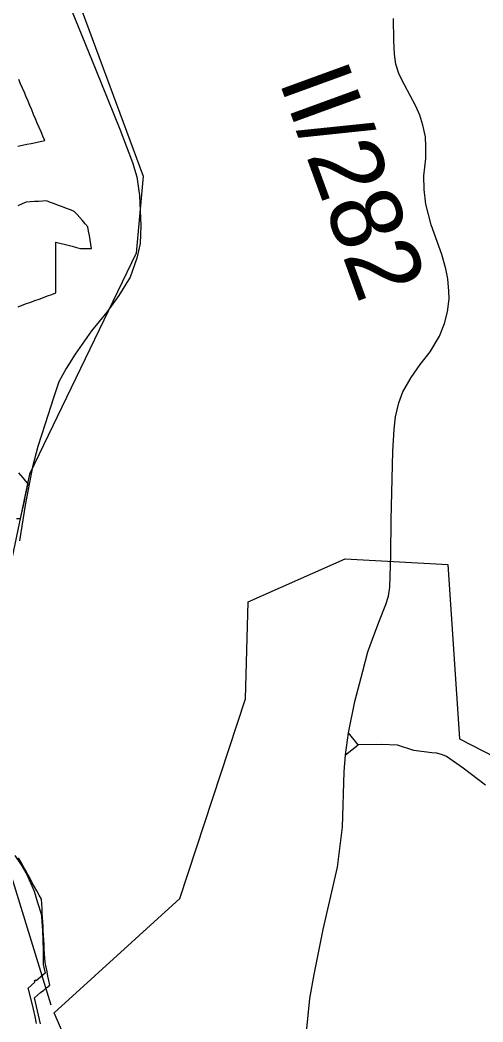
# Model space of a CAD drawing. Extents: x -789162 to -606354, y -1062736 to -945481.
# Drawn here: x -678773 to -677802, y -994612 to -992510 of the extents above; entities that cross this region are included whole.
import ezdxf

# ---------------------------------------------------------------- set-up
doc = ezdxf.new("R2010")
doc.units = 0
for name, color, linetype in [('_SIRSI VZTAHY_CYKLOTRASY MISTNI S', 7, 'Continuous'), ('_SIRSI VZTAHY_NATURA_EVL', 7, 'Continuous'), ('_SIRSI VZTAHY_SILNICE I a II TRIDY_STAV POPIS', 7, 'Continuous'), ('_SIRSI VZTAHY_SILNICE II TRIDY_STAV', 7, 'Continuous'), ('_SIRSI VZTAHY_SILNICE III TRIDY_STAV', 7, 'Continuous'), ('_SIRSI VZTAHY_USES_RBC_S', 7, 'Continuous')]:
    doc.layers.add(name, color=color, linetype=linetype)

msp = doc.modelspace()

# ---------------------------------------------------------------- linework, layer by layer
at = {"layer": '_SIRSI VZTAHY_CYKLOTRASY MISTNI S'}
for points in [[(-678759.8, -990710.2), (-678845.3, -990836.8), (-679139.4, -990833.4), (-679317.2, -990888.2), (-679027.6, -991073.5), (-678942.1, -991337), (-678791.7, -991534), (-678760.9, -991818), (-678830.4, -992067.1), (-678684.3, -992378), (-678514.4, -992837.7), (-678529.1, -992998.8), (-678752.6, -993462.6), (-678839.7, -993873), (-678895.5, -993968.5), (-678708.1, -994576.2)], [(-678593.3, -995993.9), (-678748.9, -995832.2), (-678545.4, -995658.5), (-678527.5, -995508.8), (-678359.9, -995622.6), (-678449.7, -995413), (-678413.8, -995257.3), (-678701, -994592.6), (-678437.7, -994353.1), (-678300, -993933.9), (-678294.1, -993730.3), (-678090.6, -993640.5), (-677875.1, -993652.4), (-677851.2, -994017.7), (-677653.7, -994119.5), (-677432.3, -994053.7), (-677222.8, -993945.9), (-677079.2, -993790.2), (-676932.3, -993551.1), (-676732.1, -993520.7), (-676223.4, -993784.2), (-676067.8, -993418.9), (-675894.3, -993311.1), (-675764.1, -993235.1)]]:
    msp.add_lwpolyline(points, dxfattribs=at)
at = {"layer": '_SIRSI VZTAHY_NATURA_EVL'}
for points in [[(-678776.9, -992774.6), (-678767.6, -992772.6), (-678758.2, -992770.6), (-678748.9, -992768.6), (-678739.5, -992766.6), (-678730.2, -992764.6), (-678720.8, -992762.6), (-678724.7, -992753.5), (-678728.6, -992744.3), (-678732.5, -992735.2), (-678736.4, -992726.1), (-678740.2, -992716.9), (-678744.1, -992707.8), (-678748, -992698.6), (-678751.9, -992689.5), (-678755.7, -992680.3), (-678759.6, -992671.2), (-678763.5, -992662), (-678767.4, -992652.9), (-678771.3, -992643.8), (-678775.1, -992634.6)], [(-678776.6, -993111.3), (-678767.8, -993108.1), (-678759, -993104.9), (-678750.2, -993101.7), (-678741.3, -993098.4), (-678732.5, -993095.2), (-678723.7, -993092), (-678714.8, -993088.8), (-678706, -993085.6), (-678697.2, -993082.4), (-678697.2, -993073.7), (-678697.2, -993064.9), (-678697.3, -993056.2), (-678697.3, -993046.5), (-678697.3, -993036.8), (-678697.4, -993028.1), (-678697.4, -993019.4), (-678697.4, -993010.8), (-678697.5, -993002.1), (-678697.5, -992993.4), (-678697.5, -992984.7), (-678697.6, -992976), (-678688.9, -992978.2), (-678680.3, -992980.3), (-678671.7, -992982.5), (-678663.1, -992984.6), (-678654.4, -992986.8), (-678645.8, -992989), (-678638.1, -992989), (-678630.3, -992989), (-678622.5, -992989), (-678624.1, -992979.9), (-678625.7, -992970.8), (-678627.2, -992961.8), (-678628.8, -992952.7), (-678630.3, -992943.7), (-678636, -992937.2), (-678641.7, -992930.8), (-678647.4, -992924.3), (-678653.1, -992917.8), (-678658.8, -992911.4), (-678667.1, -992908.2), (-678675.4, -992905.1), (-678683.7, -992901.9), (-678692, -992898.8), (-678700.3, -992895.7), (-678708.6, -992892.5), (-678717, -992889.4), (-678725.5, -992889.9), (-678734, -992890.4), (-678742.6, -992890.9), (-678751.1, -992891.4), (-678759.6, -992892), (-678768.4, -992895.8), (-678777.2, -992899.7)], [(-678780.3, -993555.8), (-678771.3, -993555.4), (-678769.3, -993546.3), (-678767.4, -993537.3), (-678765.4, -993528.2), (-678763.5, -993519.2), (-678761.6, -993510.1), (-678759.6, -993501.1), (-678757.7, -993492), (-678755.7, -993483), (-678760.6, -993477.1), (-678765.4, -993471.3), (-678770.3, -993465.5), (-678775.1, -993459.7)], [(-678729.7, -994615.9), (-678731.8, -994606.8), (-678734, -994597.6), (-678736.1, -994588.5), (-678738.2, -994579.3), (-678740.3, -994570.2), (-678742.4, -994561), (-678735.9, -994555.7), (-678729.4, -994550.4), (-678722.9, -994545), (-678716.4, -994539.7), (-678709.8, -994534.4), (-678711.9, -994525), (-678714, -994515.6), (-678716, -994506.1), (-678718.1, -994496.7), (-678720.1, -994487.3), (-678720.7, -994477.8), (-678721.2, -994468.3), (-678721.7, -994458.8), (-678722.3, -994449.3), (-678722.8, -994439.9), (-678723.3, -994430.4), (-678723.8, -994420.9), (-678724.4, -994411.4), (-678724.9, -994402), (-678725.4, -994392.5), (-678725.9, -994383), (-678726.5, -994373.5), (-678727, -994364.1), (-678727.5, -994354.6), (-678732.3, -994345.9), (-678737.2, -994337.1), (-678742, -994328.4), (-678746.8, -994319.7), (-678751.6, -994310.9), (-678756.4, -994302.2), (-678761.2, -994293.5), (-678766.1, -994284.7), (-678770.9, -994276), (-678775.7, -994267.3)]]:
    msp.add_lwpolyline(points, dxfattribs=at)
at = {"layer": '_SIRSI VZTAHY_SILNICE II TRIDY_STAV'}
for points in [[(-678083.7, -994005.2), (-678070.3, -993939.4), (-678053.4, -993876.2), (-678043, -993835.5), (-678033.6, -993808.6), (-678019.8, -993772.8), (-678005.6, -993736.3), (-678000.1, -993718.9), (-677997.2, -993699.5), (-677994.6, -993632.1), (-677994.3, -993558.2), (-677990.6, -993414.9), (-677988, -993368.2), (-677985.1, -993342.1), (-677978.4, -993312.8), (-677969.6, -993290.1), (-677952.3, -993259.8), (-677933.6, -993232.3), (-677912.6, -993205.9), (-677892.6, -993173.3), (-677882.3, -993146.2), (-677875.9, -993122), (-677872.9, -993094.9), (-677873.1, -993078.4), (-677875.5, -993052.6), (-677879.7, -993031.6), (-677887.7, -993001.5), (-677910.1, -992939.5), (-677921.3, -992896.1), (-677924.9, -992865.4), (-677925.6, -992836.7), (-677921.6, -992800.1), (-677921.3, -992775.5), (-677922.3, -992754.8), (-677927.5, -992730.6), (-677934.2, -992709.7), (-677942.6, -992690.6), (-677966.2, -992645.7), (-677977.8, -992624.1), (-677984.3, -992602.5), (-677987.2, -992581.2), (-677988.5, -992552.8), (-677989.1, -992506.7)], [(-678090.2, -994051.5), (-678083.7, -994005.2)], [(-678264.5, -995171.6), (-678255.1, -995156.4), (-678234.6, -995123.7), (-678209, -995087.8), (-678199, -995067.8), (-678191.8, -995044.5), (-678185.7, -994999.5), (-678183.6, -994904.5), (-678175.6, -994709.1), (-678171.7, -994633.2), (-678164.9, -994562.9), (-678156, -994512), (-678136.9, -994417.9), (-678106.5, -994287.3), (-678096.5, -994203), (-678093, -994087), (-678090.2, -994051.5)]]:
    msp.add_lwpolyline(points, dxfattribs=at)
at = {"layer": '_SIRSI VZTAHY_SILNICE III TRIDY_STAV'}
for points in [[(-678664.5, -992489), (-678613.7, -992614.1), (-678563.2, -992738.9), (-678536.9, -992809.1), (-678527.3, -992838.9), (-678521.9, -992878.3), (-678519.1, -992941.2), (-678520.3, -992979), (-678527.3, -993009.4), (-678541.6, -993049.1), (-678565.2, -993087.6), (-678590.7, -993122.7), (-678622.6, -993162.2), (-678656.8, -993210.6), (-678675.9, -993241.2), (-678690.9, -993268.8), (-678702.3, -993302.2), (-678719.9, -993357.1), (-678735.3, -993404.4), (-678746.7, -993447.6), (-678761.7, -993527.6), (-678773.9, -993602.5)], [(-678063.3, -994030.3), (-678083.7, -994005.2)], [(-678090.2, -994051.5), (-678063.3, -994030.3)], [(-677796.3, -994115.1), (-677842.9, -994079.4), (-677878.5, -994055.3), (-677886.7, -994051.5), (-677898.4, -994048.2), (-677908.6, -994047.1), (-677947, -994042.6), (-677981.3, -994031.1), (-678015.1, -994029.8), (-678063.3, -994030.3)]]:
    msp.add_lwpolyline(points, dxfattribs=at)
at = {"layer": '_SIRSI VZTAHY_USES_RBC_S'}
msp.add_lwpolyline([(-678783.2, -994262.7), (-678769.9, -994282.5), (-678758.6, -994302.2), (-678743.1, -994337.3), (-678735.7, -994361), (-678728.3, -994384.8), (-678727.8, -994391.6), (-678725.2, -994420.2), (-678724.1, -994462.1), (-678723.9, -994491.4), (-678719.8, -994509.3), (-678738.9, -994525.7), (-678739.7, -994524.5), (-678743, -994526.6), (-678741.7, -994528.6), (-678756.2, -994541.4), (-678755.4, -994542.7), (-678745.1, -994585.3), (-678741.5, -994600.3), (-678738.5, -994615.4)], dxfattribs=at)

# ---------------------------------------------------------------- texts
at = {"layer": '_SIRSI VZTAHY_SILNICE I a II TRIDY_STAV POPIS'}
msp.add_text('II/282', height=150, rotation=290.0248, dxfattribs=at).set_placement((-678230.6, -992636.7))

doc.saveas('drawing.dxf')
